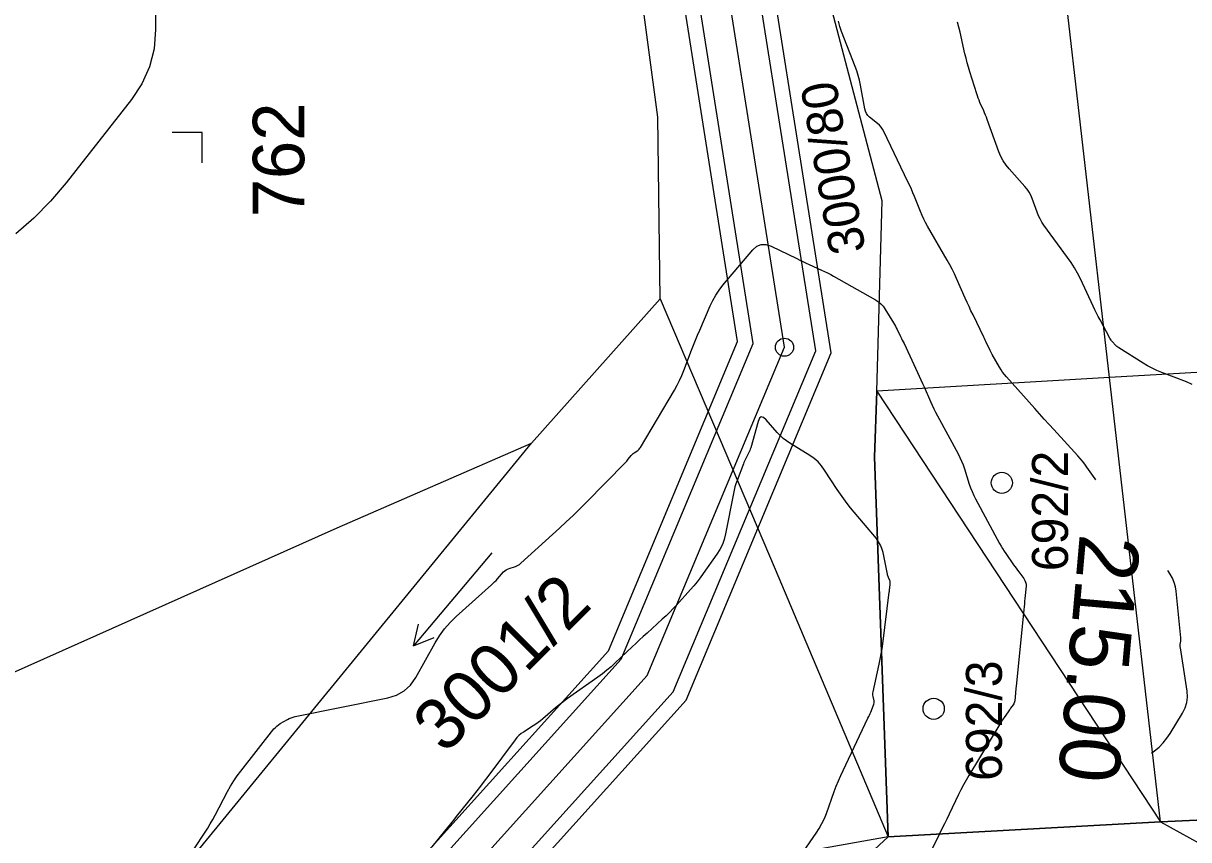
# Model space of a CAD drawing. Extents: x -534481 to -534256, y -1190577 to -1190138.
# Drawn here: x -534403.93 to -534384.66, y -1190505.1 to -1190491.61 of the extents above; entities that cross this region are included whole.
import ezdxf

# ---------------------------------------------------------------- set-up
doc = ezdxf.new("R2010")
doc.units = 0
for name, color, linetype in [('0_kroužky', 7, 'Continuous'), ('30', 7, 'Continuous'), ('31', 7, 'Continuous'), ('40', 7, 'Continuous'), ('_N_osa', 7, 'Continuous'), ('_tenka', 7, 'Continuous'), ('Hranice parcel', 7, 'Continuous'), ('Parcelní čísla', 7, 'Continuous'), ('Polygon budovy', 7, 'Continuous'), ('Značky budov', 7, 'Continuous'), ('Značky kultur', 7, 'Continuous')]:
    doc.layers.add(name, color=color, linetype=linetype)

msp = doc.modelspace()

# ---------------------------------------------------------------- linework, layer by layer
at = {"layer": '0_kroužky'}
msp.add_circle((-534391.346, -1190496.962), 0.15, dxfattribs=at)
msp.add_circle((-534391.346, -1190496.962), 0.15, dxfattribs=at)
msp.add_circle((-534391.346, -1190496.962), 0.15, dxfattribs=at)
msp.add_circle((-534391.346, -1190496.962), 0.15, dxfattribs=at)
msp.add_circle((-534391.346, -1190496.962), 0.15, dxfattribs=at)
msp.add_circle((-534391.346, -1190496.962), 0.15, dxfattribs=at)
at = {"layer": '30'}
for points in [[(-534401.743, -1190490.295), (-534401.743, -1190491.711), (-534401.768, -1190492.026), (-534401.843, -1190492.324), (-534401.968, -1190492.605), (-534402.143, -1190492.868), (-534403.221, -1190494.245), (-534403.478, -1190494.548), (-534403.756, -1190494.829), (-534404.054, -1190495.088)], [(-534386.196, -1190499.156), (-534386.207, -1190499.14), (-534386.347, -1190498.943), (-534386.382, -1190498.894), (-534386.42, -1190498.847), (-534386.458, -1190498.801), (-534386.498, -1190498.755), (-534386.892, -1190498.325), (-534386.971, -1190498.238), (-534387.05, -1190498.151), (-534387.128, -1190498.064), (-534387.207, -1190497.977), (-534387.678, -1190497.449), (-534387.71, -1190497.412), (-534387.739, -1190497.374), (-534387.766, -1190497.334), (-534387.791, -1190497.292), (-534387.91, -1190497.084), (-534387.923, -1190497.061), (-534387.936, -1190497.037), (-534387.948, -1190497.014), (-534387.959, -1190496.99), (-534388.005, -1190496.893), (-534388.016, -1190496.869), (-534388.028, -1190496.845), (-534388.04, -1190496.82), (-534388.051, -1190496.796), (-534388.229, -1190496.429), (-534388.263, -1190496.36), (-534388.295, -1190496.29), (-534388.327, -1190496.22), (-534388.359, -1190496.15), (-534388.502, -1190495.826), (-534388.537, -1190495.749), (-534388.574, -1190495.673), (-534388.613, -1190495.599), (-534388.655, -1190495.525), (-534388.981, -1190494.96), (-534389.014, -1190494.902), (-534389.044, -1190494.842), (-534389.072, -1190494.782), (-534389.098, -1190494.72), (-534389.197, -1190494.472), (-534389.222, -1190494.41), (-534389.248, -1190494.348), (-534389.276, -1190494.288), (-534389.304, -1190494.227), (-534389.706, -1190493.394), (-534389.727, -1190493.358), (-534389.75, -1190493.324), (-534389.777, -1190493.293), (-534389.808, -1190493.265), (-534389.938, -1190493.158), (-534389.967, -1190493.129), (-534389.991, -1190493.097), (-534390.007, -1190493.061), (-534390.018, -1190493.022), (-534390.09, -1190492.627), (-534390.106, -1190492.549), (-534390.127, -1190492.471), (-534390.151, -1190492.394), (-534390.178, -1190492.318), (-534390.405, -1190491.744), (-534390.433, -1190491.658), (-534390.451, -1190491.57)], [(-534391.031, -1190505.3), (-534390.821, -1190504.996), (-534390.771, -1190504.919), (-534390.726, -1190504.839), (-534390.687, -1190504.756), (-534390.653, -1190504.671), (-534390.523, -1190504.308), (-534390.489, -1190504.219), (-534390.454, -1190504.131), (-534390.417, -1190504.044), (-534390.377, -1190503.958), (-534389.966, -1190503.093), (-534389.954, -1190503.068), (-534389.943, -1190503.044), (-534389.932, -1190503.019), (-534389.921, -1190502.994), (-534389.872, -1190502.879), (-534389.866, -1190502.862), (-534389.863, -1190502.844), (-534389.863, -1190502.826), (-534389.865, -1190502.808), (-534389.881, -1190502.735), (-534389.884, -1190502.717), (-534389.885, -1190502.699), (-534389.884, -1190502.68), (-534389.881, -1190502.662), (-534389.78, -1190502.2), (-534389.762, -1190502.117), (-534389.747, -1190502.033), (-534389.733, -1190501.949), (-534389.722, -1190501.865), (-534389.613, -1190501.013), (-534389.61, -1190500.996), (-534389.608, -1190500.979), (-534389.607, -1190500.962), (-534389.605, -1190500.946), (-534389.597, -1190500.873), (-534389.596, -1190500.859), (-534389.597, -1190500.845), (-534389.6, -1190500.832), (-534389.605, -1190500.819), (-534389.628, -1190500.767), (-534389.634, -1190500.754), (-534389.638, -1190500.741), (-534389.642, -1190500.727), (-534389.645, -1190500.713), (-534389.717, -1190500.355), (-534389.734, -1190500.292), (-534389.758, -1190500.233), (-534389.789, -1190500.178), (-534389.827, -1190500.126), (-534390.252, -1190499.617), (-534390.311, -1190499.544), (-534390.367, -1190499.47), (-534390.421, -1190499.394), (-534390.473, -1190499.316), (-534390.682, -1190498.992), (-534390.733, -1190498.922), (-534390.79, -1190498.858), (-534390.855, -1190498.802), (-534390.927, -1190498.753), (-534391.256, -1190498.551), (-534391.314, -1190498.512), (-534391.369, -1190498.469), (-534391.42, -1190498.422), (-534391.468, -1190498.371), (-534391.651, -1190498.16), (-534391.694, -1190498.122), (-534391.73, -1190498.114), (-534391.759, -1190498.136), (-534391.781, -1190498.189), (-534391.904, -1190498.623), (-534391.911, -1190498.646), (-534391.92, -1190498.669), (-534391.929, -1190498.692), (-534391.94, -1190498.714), (-534391.985, -1190498.801), (-534391.996, -1190498.823), (-534392.006, -1190498.845), (-534392.016, -1190498.868), (-534392.025, -1190498.89), (-534392.129, -1190499.164), (-534392.148, -1190499.218), (-534392.165, -1190499.272), (-534392.179, -1190499.327), (-534392.191, -1190499.383), (-534392.319, -1190500.049), (-534392.341, -1190500.139), (-534392.373, -1190500.225), (-534392.413, -1190500.308), (-534392.463, -1190500.386), (-534392.689, -1190500.706), (-534392.739, -1190500.775), (-534392.791, -1190500.841), (-534392.844, -1190500.907), (-534392.9, -1190500.97), (-534393.127, -1190501.222), (-534393.184, -1190501.284), (-534393.243, -1190501.344), (-534393.304, -1190501.404), (-534393.366, -1190501.461), (-534393.617, -1190501.688), (-534393.68, -1190501.745), (-534393.742, -1190501.802), (-534393.804, -1190501.86), (-534393.866, -1190501.918), (-534394.144, -1190502.182), (-534394.212, -1190502.245), (-534394.282, -1190502.304), (-534394.355, -1190502.361), (-534394.429, -1190502.416), (-534394.933, -1190502.772), (-534394.984, -1190502.809), (-534395.033, -1190502.847), (-534395.082, -1190502.886), (-534395.13, -1190502.926), (-534395.343, -1190503.109), (-534395.38, -1190503.139), (-534395.418, -1190503.169), (-534395.458, -1190503.196), (-534395.498, -1190503.222), (-534395.661, -1190503.324), (-534395.701, -1190503.351), (-534395.737, -1190503.381), (-534395.77, -1190503.415), (-534395.8, -1190503.452), (-534396.25, -1190504.057), (-534396.31, -1190504.137), (-534396.371, -1190504.217), (-534396.432, -1190504.296), (-534396.494, -1190504.375), (-534396.771, -1190504.723), (-534396.82, -1190504.784), (-534396.869, -1190504.844), (-534396.917, -1190504.905), (-534396.966, -1190504.966), (-534397.175, -1190505.224)], [(-534385.279, -1190503.674), (-534385.229, -1190503.635), (-534385.154, -1190503.572), (-534385.087, -1190503.502), (-534385.025, -1190503.427), (-534384.97, -1190503.347), (-534384.764, -1190503.012), (-534384.72, -1190502.926), (-534384.694, -1190502.838), (-534384.684, -1190502.746), (-534384.69, -1190502.65), (-534384.801, -1190501.935), (-534384.803, -1190501.921), (-534384.803, -1190501.907), (-534384.803, -1190501.893), (-534384.802, -1190501.879), (-534384.796, -1190501.822), (-534384.795, -1190501.808), (-534384.795, -1190501.794), (-534384.795, -1190501.78), (-534384.796, -1190501.766), (-534384.871, -1190500.998), (-534384.883, -1190500.923), (-534384.904, -1190500.851), (-534384.933, -1190500.782), (-534384.972, -1190500.716), (-534385.011, -1190500.656)]]:
    msp.add_lwpolyline(points, dxfattribs=at)
at = {"layer": '31'}
for points in [[(-534384.605, -1190497.576), (-534384.698, -1190497.535), (-534385.11, -1190497.378), (-534385.189, -1190497.346), (-534385.267, -1190497.31), (-534385.342, -1190497.27), (-534385.416, -1190497.226), (-534385.821, -1190496.973), (-534385.836, -1190496.962), (-534385.85, -1190496.951), (-534385.864, -1190496.939), (-534385.876, -1190496.926), (-534385.925, -1190496.872), (-534385.937, -1190496.858), (-534385.947, -1190496.843), (-534385.957, -1190496.828), (-534385.966, -1190496.812), (-534386.129, -1190496.51), (-534386.159, -1190496.454), (-534386.188, -1190496.397), (-534386.216, -1190496.341), (-534386.243, -1190496.283), (-534386.454, -1190495.832), (-534386.5, -1190495.739), (-534386.551, -1190495.649), (-534386.606, -1190495.561), (-534386.665, -1190495.476), (-534387.056, -1190494.942), (-534387.09, -1190494.892), (-534387.12, -1190494.84), (-534387.146, -1190494.787), (-534387.168, -1190494.731), (-534387.249, -1190494.504), (-534387.272, -1190494.449), (-534387.299, -1190494.397), (-534387.332, -1190494.348), (-534387.37, -1190494.302), (-534387.63, -1190494.015), (-534387.683, -1190493.95), (-534387.729, -1190493.881), (-534387.768, -1190493.808), (-534387.801, -1190493.73), (-534387.995, -1190493.194), (-534388.008, -1190493.158), (-534388.022, -1190493.123), (-534388.037, -1190493.088), (-534388.052, -1190493.053), (-534388.114, -1190492.914), (-534388.13, -1190492.879), (-534388.144, -1190492.844), (-534388.156, -1190492.808), (-534388.168, -1190492.772), (-534388.282, -1190492.406), (-534388.304, -1190492.333), (-534388.325, -1190492.259), (-534388.344, -1190492.185), (-534388.362, -1190492.11), (-534388.443, -1190491.752), (-534388.464, -1190491.668), (-534388.488, -1190491.585)], [(-534401.104, -1190505.256), (-534400.924, -1190504.982), (-534400.88, -1190504.913), (-534400.838, -1190504.842), (-534400.797, -1190504.771), (-534400.758, -1190504.699), (-534400.552, -1190504.308), (-534400.504, -1190504.22), (-534400.451, -1190504.134), (-534400.394, -1190504.051), (-534400.334, -1190503.97), (-534399.786, -1190503.274), (-534399.763, -1190503.248), (-534399.739, -1190503.225), (-534399.712, -1190503.204), (-534399.683, -1190503.186), (-534399.563, -1190503.118), (-534399.533, -1190503.102), (-534399.502, -1190503.089), (-534399.469, -1190503.079), (-534399.436, -1190503.07), (-534397.901, -1190502.759), (-534397.758, -1190502.714), (-534397.633, -1190502.644), (-534397.528, -1190502.547), (-534397.442, -1190502.423), (-534397.122, -1190501.852), (-534397.048, -1190501.732), (-534396.965, -1190501.619), (-534396.873, -1190501.513), (-534396.772, -1190501.415), (-534396.19, -1190500.891), (-534396.165, -1190500.868), (-534396.14, -1190500.843), (-534396.115, -1190500.818), (-534396.092, -1190500.792), (-534395.989, -1190500.676), (-534395.969, -1190500.657), (-534395.948, -1190500.642), (-534395.925, -1190500.629), (-534395.9, -1190500.62), (-534395.795, -1190500.588), (-534395.77, -1190500.579), (-534395.746, -1190500.567), (-534395.724, -1190500.552), (-534395.703, -1190500.535), (-534395.065, -1190499.954), (-534394.953, -1190499.85), (-534394.842, -1190499.745), (-534394.733, -1190499.638), (-534394.625, -1190499.53), (-534393.978, -1190498.871), (-534393.965, -1190498.858), (-534393.952, -1190498.844), (-534393.941, -1190498.829), (-534393.929, -1190498.815), (-534393.883, -1190498.754), (-534393.872, -1190498.741), (-534393.86, -1190498.728), (-534393.846, -1190498.717), (-534393.832, -1190498.707), (-534393.773, -1190498.668), (-534393.759, -1190498.657), (-534393.746, -1190498.646), (-534393.735, -1190498.632), (-534393.725, -1190498.618), (-534393.164, -1190497.67), (-534393.12, -1190497.592), (-534393.079, -1190497.512), (-534393.042, -1190497.431), (-534393.009, -1190497.348), (-534392.882, -1190497.012), (-534392.85, -1190496.929), (-534392.816, -1190496.845), (-534392.782, -1190496.762), (-534392.748, -1190496.68), (-534392.576, -1190496.28), (-534392.533, -1190496.188), (-534392.483, -1190496.1), (-534392.426, -1190496.016), (-534392.363, -1190495.936), (-534391.869, -1190495.353), (-534391.803, -1190495.293), (-534391.731, -1190495.262), (-534391.652, -1190495.261), (-534391.568, -1190495.289), (-534391.142, -1190495.497), (-534391.091, -1190495.522), (-534391.041, -1190495.546), (-534390.99, -1190495.57), (-534390.938, -1190495.593), (-534390.733, -1190495.686), (-534390.682, -1190495.709), (-534390.632, -1190495.734), (-534390.582, -1190495.76), (-534390.533, -1190495.787), (-534389.84, -1190496.179), (-534389.794, -1190496.209), (-534389.753, -1190496.244), (-534389.716, -1190496.284), (-534389.685, -1190496.328), (-534389.544, -1190496.557), (-534389.528, -1190496.585), (-534389.512, -1190496.613), (-534389.497, -1190496.641), (-534389.482, -1190496.67), (-534389.426, -1190496.786), (-534389.412, -1190496.815), (-534389.398, -1190496.845), (-534389.384, -1190496.874), (-534389.37, -1190496.903), (-534389.145, -1190497.38), (-534389.117, -1190497.439), (-534389.09, -1190497.499), (-534389.063, -1190497.559), (-534389.036, -1190497.619), (-534388.931, -1190497.86), (-534388.905, -1190497.92), (-534388.876, -1190497.979), (-534388.847, -1190498.038), (-534388.816, -1190498.096), (-534388.475, -1190498.727), (-534388.445, -1190498.787), (-534388.418, -1190498.847), (-534388.393, -1190498.909), (-534388.372, -1190498.972), (-534388.291, -1190499.226), (-534388.27, -1190499.288), (-534388.245, -1190499.35), (-534388.218, -1190499.411), (-534388.188, -1190499.47), (-534387.79, -1190500.206), (-534387.766, -1190500.249), (-534387.741, -1190500.291), (-534387.714, -1190500.333), (-534387.686, -1190500.374), (-534387.557, -1190500.559), (-534387.536, -1190500.588), (-534387.516, -1190500.617), (-534387.495, -1190500.646), (-534387.474, -1190500.674), (-534387.389, -1190500.788), (-534387.371, -1190500.817), (-534387.359, -1190500.848), (-534387.353, -1190500.881), (-534387.353, -1190500.915), (-534387.372, -1190501.117), (-534387.376, -1190501.162), (-534387.38, -1190501.207), (-534387.385, -1190501.253), (-534387.389, -1190501.298), (-534387.518, -1190502.57), (-534387.52, -1190502.597), (-534387.523, -1190502.625), (-534387.526, -1190502.652), (-534387.528, -1190502.68), (-534387.54, -1190502.809), (-534387.543, -1190502.826), (-534387.548, -1190502.843), (-534387.555, -1190502.859), (-534387.565, -1190502.873), (-534387.607, -1190502.931), (-534387.617, -1190502.946), (-534387.627, -1190502.96), (-534387.638, -1190502.975), (-534387.648, -1190502.989), (-534387.714, -1190503.083), (-534387.728, -1190503.104), (-534387.742, -1190503.125), (-534387.756, -1190503.146), (-534387.769, -1190503.167), (-534388.298, -1190504.043), (-534388.343, -1190504.12), (-534388.387, -1190504.199), (-534388.429, -1190504.278), (-534388.469, -1190504.359), (-534388.625, -1190504.683), (-534388.664, -1190504.764), (-534388.703, -1190504.844), (-534388.743, -1190504.925), (-534388.782, -1190505.006), (-534388.96, -1190505.368)]]:
    msp.add_lwpolyline(points, dxfattribs=at)
at = {"layer": '_N_osa'}
msp.add_lwpolyline([(-534408.105, -1190518.46), (-534393.616, -1190502.389), (-534391.346, -1190496.962), (-534392.763, -1190488.017), (-534396.655, -1190477.752), (-534402.513, -1190464.283), (-534404.757, -1190456.741), (-534408.311, -1190433.088), (-534409.248, -1190427.879), (-534409.316, -1190416.054), (-534409.076, -1190409.418), (-534409.868, -1190391.439)], dxfattribs=at)
at = {"layer": '_tenka'}
for points in [[(-534405.407, -1190514.348), (-534394.258, -1190501.982), (-534392.12, -1190496.869), (-534393.492, -1190488.211), (-534397.35, -1190478.035), (-534403.219, -1190464.54), (-534405.491, -1190456.905), (-534409.051, -1190433.21), (-534409.998, -1190427.948), (-534410.066, -1190416.042), (-534409.827, -1190409.421), (-534410.645, -1190390.84)], [(-534405.057, -1190514.333), (-534394.044, -1190502.118), (-534391.862, -1190496.9), (-534393.249, -1190488.146), (-534397.118, -1190477.94), (-534402.983, -1190464.455), (-534405.247, -1190456.85), (-534408.804, -1190433.17), (-534409.748, -1190427.925), (-534409.816, -1190416.046), (-534409.577, -1190409.42), (-534410.397, -1190390.795)], [(-534403.656, -1190514.273), (-534393.187, -1190502.661), (-534390.83, -1190497.024), (-534392.278, -1190487.888), (-534396.191, -1190477.563), (-534402.042, -1190464.111), (-534404.268, -1190456.632), (-534407.818, -1190433.007), (-534408.749, -1190427.833), (-534408.816, -1190416.061), (-534408.576, -1190409.416), (-534409.363, -1190391.537)], [(-534403.306, -1190514.257), (-534392.973, -1190502.796), (-534390.572, -1190497.055), (-534392.035, -1190487.824), (-534395.96, -1190477.469), (-534401.807, -1190464.025), (-534404.023, -1190456.578), (-534407.571, -1190432.966), (-534408.499, -1190427.81), (-534408.566, -1190416.065), (-534408.326, -1190409.415), (-534409.111, -1190391.586)]]:
    msp.add_lwpolyline(points, dxfattribs=at)
at = {"layer": 'Hranice parcel'}
for p, q in [((-534395.53, -1190498.55), (-534393.4, -1190496.16)), ((-534389.82, -1190497.69), (-534385.13, -1190504.81)), ((-534402.95, -1190507.61), (-534395.53, -1190498.55)), ((-534385.13, -1190504.81), (-534389.63, -1190505.06)), ((-534384.53, -1190504.78), (-534385.13, -1190504.81)), ((-534389.63, -1190505.06), (-534401.56, -1190515.98))]:
    msp.add_line(p, q, dxfattribs=at)
for points in [[(-534385.13, -1190504.81), (-534385.97, -1190497.46), (-534387.18, -1190486.94)], [(-534389.82, -1190497.69), (-534389.73, -1190494.54), (-534391.64, -1190487.29)], [(-534393.4, -1190496.16), (-534393.44, -1190493.16), (-534393.76, -1190490.76)], [(-534393.4, -1190496.16), (-534392, -1190499.45), (-534391.5, -1190500.63), (-534389.63, -1190505.06)], [(-534389.63, -1190505.06), (-534389.86, -1190498.78), (-534389.82, -1190497.69)], [(-534404.16, -1190502.37), (-534398.74, -1190499.95), (-534395.53, -1190498.55)], [(-534385.13, -1190504.81), (-534384.49, -1190505.16), (-534382.4, -1190506.3), (-534375.507, -1190510.084)], [(-534389.63, -1190505.06), (-534396.5, -1190506.28), (-534398.08, -1190506.56), (-534402.44, -1190507.34), (-534402.95, -1190507.61)]]:
    msp.add_lwpolyline(points, dxfattribs=at)
at = {"layer": 'Polygon budovy'}
msp.add_lwpolyline([(-534381.11, -1190486.74), (-534379.63, -1190494.14), (-534379.04, -1190497.06), (-534379.33, -1190497.08), (-534385.97, -1190497.46), (-534389.82, -1190497.69), (-534389.86, -1190498.78), (-534389.63, -1190505.06), (-534385.13, -1190504.81), (-534384.53, -1190504.78), (-534372.8, -1190504.12), (-534374.01, -1190497.07), (-534374.08, -1190496.69), (-534374.94, -1190492.52), (-534375.06, -1190491.94), (-534376.48, -1190486.28), (-534380.38, -1190486.72)], close=True, dxfattribs=at)
at = {"layer": 'Značky budov'}
for centre in [(-534387.753, -1190499.204), (-534388.88, -1190502.94)]:
    msp.add_circle(centre, 0.175, dxfattribs=at)
at = {"layer": 'Značky kultur'}
for p, q in [((-534400.971, -1190493.411), (-534401.471, -1190493.411)), ((-534400.971, -1190493.911), (-534400.971, -1190493.411)), ((-534396.186, -1190500.362), (-534397.478, -1190501.902)), ((-534397.478, -1190501.902), (-534397.396, -1190501.543)), ((-534397.478, -1190501.902), (-534397.139, -1190501.759))]:
    msp.add_line(p, q, dxfattribs=at)

# ---------------------------------------------------------------- texts
at = {"layer": '40'}
msp.add_text('215.00', height=1, rotation=264.9313, dxfattribs=at).set_placement((-534386.462, -1190500.034))
at = {"layer": 'Parcelní čísla'}
for s, height, rotation, p in [('3000/80', 0.595, 100, (-534390.001, -1190495.363)), ('762', 0.85, 90, (-534399.286, -1190494.813)), ('692/2', 0.595, 90, (-534386.659, -1190500.665)), ('3001/2', 0.85, 45, (-534396.959, -1190503.703)), ('692/3', 0.595, 90, (-534387.751, -1190504.133))]:
    msp.add_text(s, height=height, rotation=rotation, dxfattribs=at).set_placement(p)

doc.saveas('drawing.dxf')
